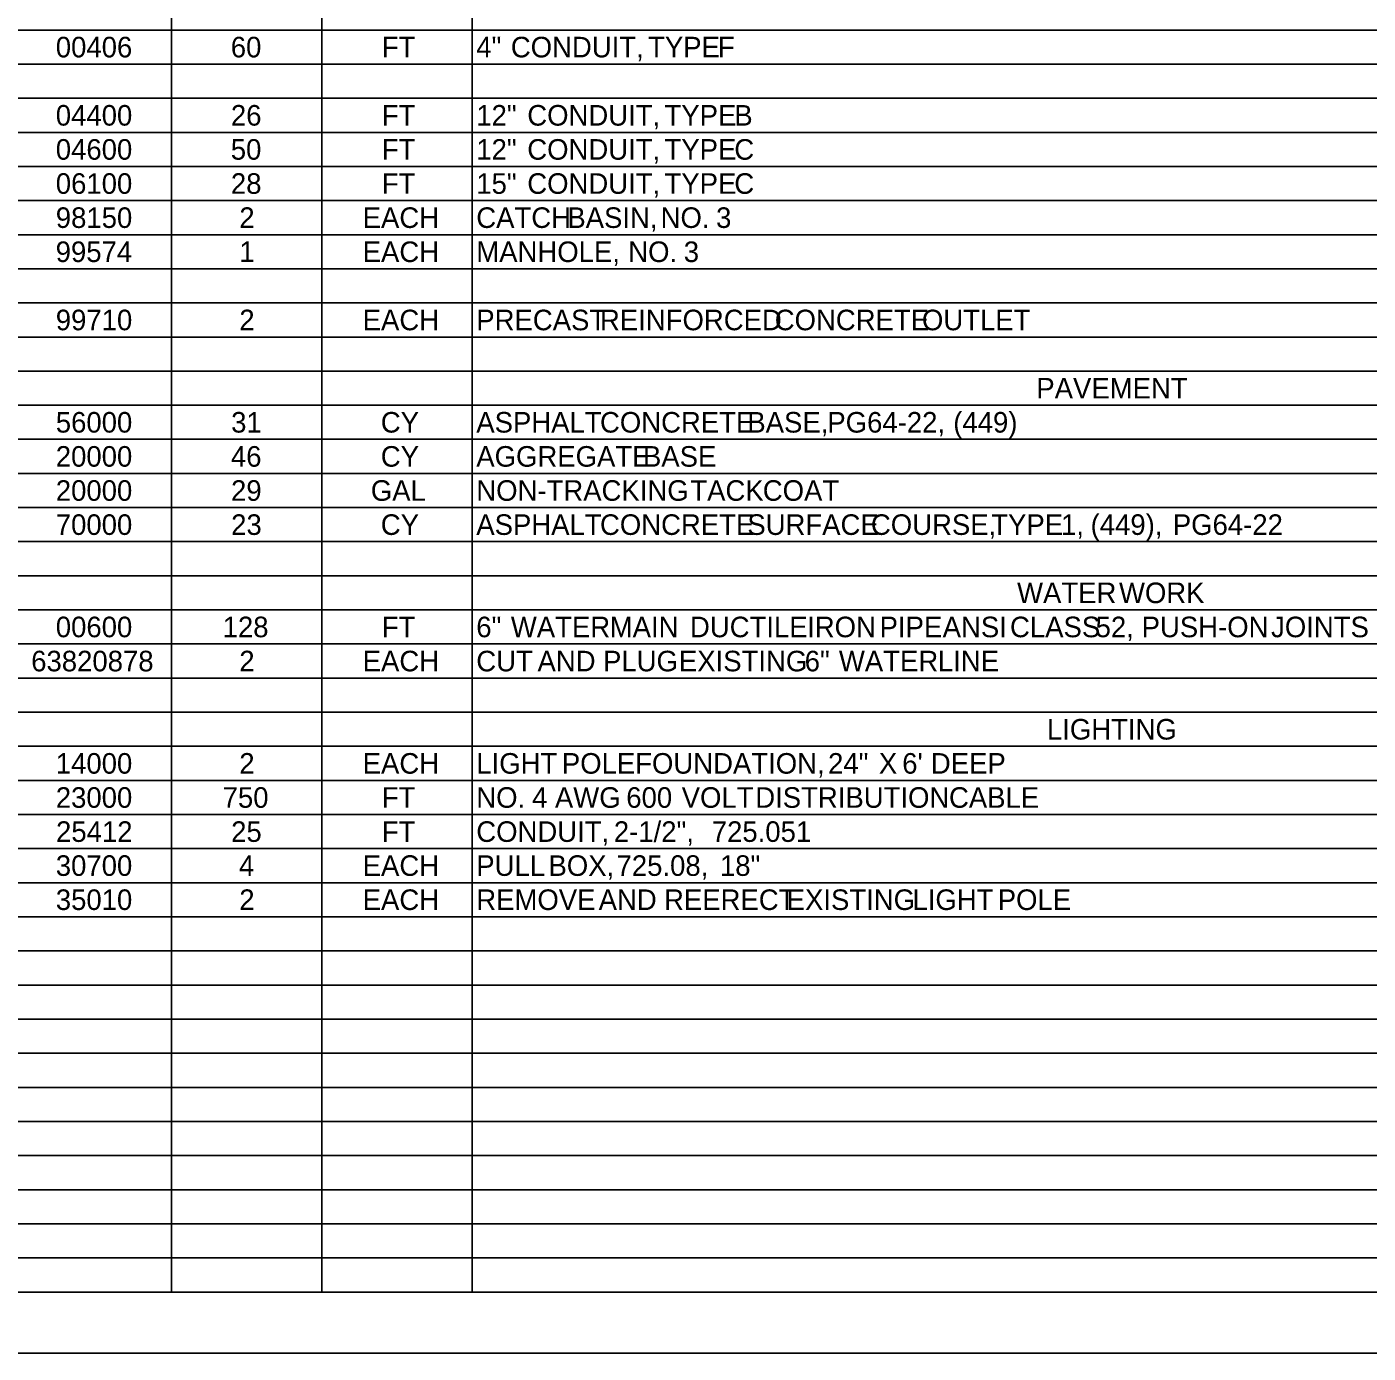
# Model space of a CAD drawing. Extents: x 0 to 34, y 0 to 22.
# Drawn here: x 16.85 to 27.86, y 0 to 10.89 of the extents above; entities that cross this region are included whole.
import ezdxf

# ---------------------------------------------------------------- set-up
doc = ezdxf.new("R2010")
doc.units = 0
for name, color, linetype in [('SH_Border', 7, 'Continuous'), ('SH_Cut_Line', 7, 'Continuous'), ('SH_Data', 7, 'Continuous')]:
    doc.layers.add(name, color=color, linetype=linetype)

msp = doc.modelspace()

# ---------------------------------------------------------------- linework, layer by layer
at = {"layer": 'SH_Border'}
msp.add_lwpolyline([(1.5, 21.5), (33.5, 21.5), (33.5, 0.5), (1.5, 0.5)], close=True, dxfattribs=at)
at = {"layer": 'SH_Cut_Line'}
msp.add_lwpolyline([(0, 0), (34, 0), (34, 22), (0, 22)], close=True, dxfattribs=at)
at = {"layer": 'SH_Data'}
for p, q in [((18.035, 0.502), (18.035, 21.5)), ((19.27, 0.502), (19.27, 21.5)), ((20.505, 0.502), (20.505, 21.5)), ((1.5, 10.861), (32, 10.861)), ((1.5, 10.581), (32, 10.581)), ((1.5, 10.301), (32, 10.301)), ((1.5, 10.021), (32, 10.021)), ((1.5, 9.741), (32, 9.741)), ((1.5, 9.461), (32, 9.461)), ((1.5, 9.181), (32, 9.181)), ((1.5, 8.901), (32, 8.901)), ((1.5, 8.621), (32, 8.621)), ((1.5, 8.341), (32, 8.341)), ((1.5, 8.062), (32, 8.062)), ((1.5, 7.782), (32, 7.782)), ((1.5, 7.502), (32, 7.502)), ((1.5, 7.222), (32, 7.222)), ((1.5, 6.942), (32, 6.942)), ((1.5, 6.662), (32, 6.662)), ((1.5, 6.382), (32, 6.382)), ((1.5, 6.102), (32, 6.102)), ((1.5, 5.822), (32, 5.822)), ((1.5, 5.542), (32, 5.542)), ((1.5, 5.262), (32, 5.262)), ((1.5, 4.982), (32, 4.982)), ((1.5, 4.702), (32, 4.702)), ((1.5, 4.422), (32, 4.422)), ((1.5, 4.142), (32, 4.142)), ((1.5, 3.862), (32, 3.862)), ((1.5, 3.582), (32, 3.582)), ((1.5, 3.302), (32, 3.302)), ((1.5, 3.022), (32, 3.022)), ((1.5, 2.742), (32, 2.742)), ((1.5, 2.462), (32, 2.462)), ((1.5, 2.182), (32, 2.182)), ((1.5, 1.902), (32, 1.902)), ((1.5, 1.622), (32, 1.622)), ((1.5, 1.342), (32, 1.342)), ((1.5, 1.062), (32, 1.062)), ((1.5, 0.782), (32, 0.782)), ((1.5, 0.502), (32, 0.502))]:
    msp.add_line(p, q, dxfattribs=at)

# ---------------------------------------------------------------- texts
for s, height, p in [('00406', 0.1689, (17.085, 10.637)), ('60', 0.1689, (18.522, 10.637)), ('FT', 0.1689, (19.762, 10.637)), ('4"', 0.1689, (20.538, 10.637)), (' CONDUIT,', 0.1689, (20.759, 10.637)), (' TYPE', 0.1689, (21.886, 10.637)), (' F', 0.1689, (22.459, 10.637)), ('04400', 0.1689, (17.085, 10.077)), ('26', 0.1689, (18.523, 10.077)), ('FT', 0.1689, (19.762, 10.077)), ('12"', 0.1689, (20.538, 10.077)), (' CONDUIT,', 0.1689, (20.894, 10.077)), (' TYPE', 0.1689, (22.021, 10.077)), (' B', 0.1689, (22.594, 10.077)), ('04600', 0.1689, (17.085, 9.797)), ('50', 0.1689, (18.522, 9.797)), ('FT', 0.1689, (19.762, 9.797)), ('12"', 0.1689, (20.538, 9.797)), (' CONDUIT,', 0.1689, (20.894, 9.797)), (' TYPE', 0.1689, (22.021, 9.797)), (' C', 0.1689, (22.594, 9.797)), ('06100', 0.1689, (17.085, 9.517)), ('28', 0.1689, (18.523, 9.517)), ('FT', 0.1689, (19.762, 9.517)), ('15"', 0.1689, (20.538, 9.517)), (' CONDUIT,', 0.1689, (20.894, 9.517)), (' TYPE', 0.1689, (22.021, 9.517)), (' C', 0.1689, (22.594, 9.517)), ('98150', 0.1689, (17.085, 9.237)), ('2', 0.169, (18.592, 9.237)), ('EACH', 0.1689, (19.605, 9.237)), ('CATCH', 0.1689, (20.538, 9.237)), (' BASIN,', 0.1689, (21.223, 9.237)), (' NO.', 0.1689, (21.989, 9.237)), (' 3', 0.1689, (22.444, 9.237)), ('99574', 0.1689, (17.084, 8.957)), ('1', 0.169, (18.592, 8.957)), ('EACH', 0.1689, (19.605, 8.957)), ('MANHOLE,', 0.1689, (20.538, 8.957)), (' NO.', 0.1689, (21.723, 8.957)), (' 3', 0.1689, (22.179, 8.957)), ('99710', 0.1689, (17.085, 8.397)), ('2', 0.169, (18.592, 8.397)), ('EACH', 0.1689, (19.605, 8.397)), ('PRECAST', 0.1689, (20.538, 8.397)), (' REINFORCED', 0.16891, (21.491, 8.397)), (' CONCRETE', 0.1689, (22.926, 8.397)), (' OUTLET', 0.1689, (24.135, 8.397)), ('PAVEMENT', 0.1689, (25.137, 7.837)), ('56000', 0.1689, (17.085, 7.557)), ('31', 0.1689, (18.525, 7.557)), ('CY', 0.1689, (19.754, 7.557)), ('ASPHALT', 0.1689, (20.538, 7.557)), (' CONCRETE', 0.1689, (21.491, 7.557)), (' BASE,', 0.1689, (22.701, 7.557)), (' PG64-22,', 0.1689, (23.358, 7.557)), (' (449)', 0.1689, (24.392, 7.557)), ('20000', 0.1689, (17.085, 7.277)), ('46', 0.1689, (18.523, 7.277)), ('CY', 0.1689, (19.754, 7.277)), ('AGGREGATE', 0.1689, (20.538, 7.277)), (' BASE', 0.1689, (21.844, 7.277)), ('20000', 0.1689, (17.085, 6.997)), ('29', 0.1689, (18.524, 6.997)), ('GAL', 0.1689, (19.672, 6.997)), ('NON-TRACKING', 0.16891, (20.538, 6.997)), (' TACK', 0.1689, (22.233, 6.997)), (' COAT', 0.1689, (22.828, 6.997)), ('70000', 0.1689, (17.085, 6.717)), ('23', 0.1689, (18.525, 6.717)), ('CY', 0.1689, (19.754, 6.717)), ('ASPHALT', 0.1689, (20.538, 6.717)), (' CONCRETE', 0.1689, (21.491, 6.717)), (' SURFACE', 0.1689, (22.701, 6.717)), (' COURSE,', 0.1689, (23.716, 6.717)), (' TYPE', 0.1689, (24.704, 6.717)), (' 1,', 0.1689, (25.277, 6.717)), (' (449),', 0.1689, (25.52, 6.717)), (' PG64-22', 0.1689, (26.195, 6.717)), ('WATER', 0.1689, (24.979, 6.157)), (' WORK', 0.1689, (25.753, 6.157)), ('00600', 0.1689, (17.085, 5.877)), ('128', 0.1689, (18.455, 5.877)), ('FT', 0.1689, (19.762, 5.877)), ('6"', 0.1689, (20.538, 5.877)), (' WATER', 0.1689, (20.759, 5.877)), (' MAIN', 0.1689, (21.571, 5.877)), (' DUCTILE', 0.1689, (22.23, 5.877)), (' IRON', 0.1689, (23.192, 5.877)), (' PIPE', 0.1689, (23.787, 5.877)), (' ANSI', 0.1689, (24.305, 5.877)), (' CLASS', 0.1689, (24.858, 5.877)), (' 52,', 0.1689, (25.561, 5.877)), (' PUSH-ON', 0.1689, (25.939, 5.877)), (' JOINTS', 0.1689, (27.002, 5.877)), ('63820878', 0.1689, (16.883, 5.597)), ('2', 0.169, (18.592, 5.597)), ('EACH', 0.1689, (19.605, 5.597)), ('CUT', 0.1689, (20.538, 5.597)), (' AND', 0.1689, (20.978, 5.597)), (' PLUG', 0.1689, (21.516, 5.597)), (' EXISTING', 0.1689, (22.139, 5.597)), (' 6"', 0.1689, (23.172, 5.597)), (' WATER', 0.1689, (23.453, 5.597)), (' LINE', 0.1689, (24.266, 5.597)), ('LIGHTING', 0.1689, (25.224, 5.037)), ('14000', 0.1689, (17.085, 4.757)), ('2', 0.169, (18.592, 4.757)), ('EACH', 0.1689, (19.605, 4.757)), ('LIGHT', 0.1689, (20.538, 4.757)), (' POLE', 0.1689, (21.178, 4.757)), (' FOUNDATION,', 0.16891, (21.78, 4.757)), (' 24"', 0.1689, (23.364, 4.757)), (' X', 0.1689, (23.781, 4.757)), (" 6'", 0.1689, (23.973, 4.757)), (' DEEP', 0.1689, (24.208, 4.757)), ('23000', 0.1689, (17.085, 4.477)), ('750', 0.1689, (18.455, 4.477)), ('FT', 0.1689, (19.762, 4.477)), ('NO.', 0.1689, (20.538, 4.477)), (' 4', 0.1689, (20.933, 4.477)), (' AWG', 0.1689, (21.121, 4.477)), (' 600', 0.1689, (21.707, 4.477)), (' VOLT', 0.1689, (22.162, 4.477)), (' DISTRIBUTION', 0.16891, (22.766, 4.477)), (' CABLE', 0.1689, (24.357, 4.477)), ('25412', 0.1689, (17.087, 4.197)), ('25', 0.1689, (18.525, 4.197)), ('FT', 0.1689, (19.762, 4.197)), ('CONDUIT,', 0.1689, (20.538, 4.197)), (' 2-1/2",', 0.1689, (21.605, 4.197)), (' 725.051', 0.1689, (22.409, 4.197)), ('30700', 0.1689, (17.085, 3.918)), ('4', 0.169, (18.589, 3.918)), ('EACH', 0.1689, (19.605, 3.918)), ('PULL', 0.1689, (20.538, 3.918)), (' BOX,', 0.1689, (21.068, 3.918)), (' 725.08,', 0.1689, (21.627, 3.918)), (' 18"', 0.1689, (22.476, 3.918)), ('35010', 0.1689, (17.085, 3.638)), ('2', 0.169, (18.592, 3.638)), ('EACH', 0.1689, (19.605, 3.638)), ('REMOVE', 0.1689, (20.538, 3.638)), (' AND', 0.1689, (21.48, 3.638)), (' REERECT', 0.1689, (22.017, 3.638)), (' EXISTING', 0.1689, (23.024, 3.638)), (' LIGHT', 0.1689, (24.057, 3.638)), (' POLE', 0.1689, (24.757, 3.638))]:
    msp.add_text(s, height=height, dxfattribs=at).set_placement(p)

doc.saveas('drawing.dxf')
